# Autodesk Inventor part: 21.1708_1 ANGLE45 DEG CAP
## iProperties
Created: 2007-01
Part Number: 21.1708_1 ANGLE45 DEG CAP
Document SubType Name: Modeling
Designer: Andy Moles
Material: ABS Plastic
Mass: 7.4014 g
Surface Area: 70.9467 cm^2
Volume: 6.98245 cm^3
Density: 1.06 g/cm^3
Author: Andy Moles
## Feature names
1. Extrusion1
2. Extrusion2
3. Extrusion3
4. Extrusion4
5. Extrusion6
